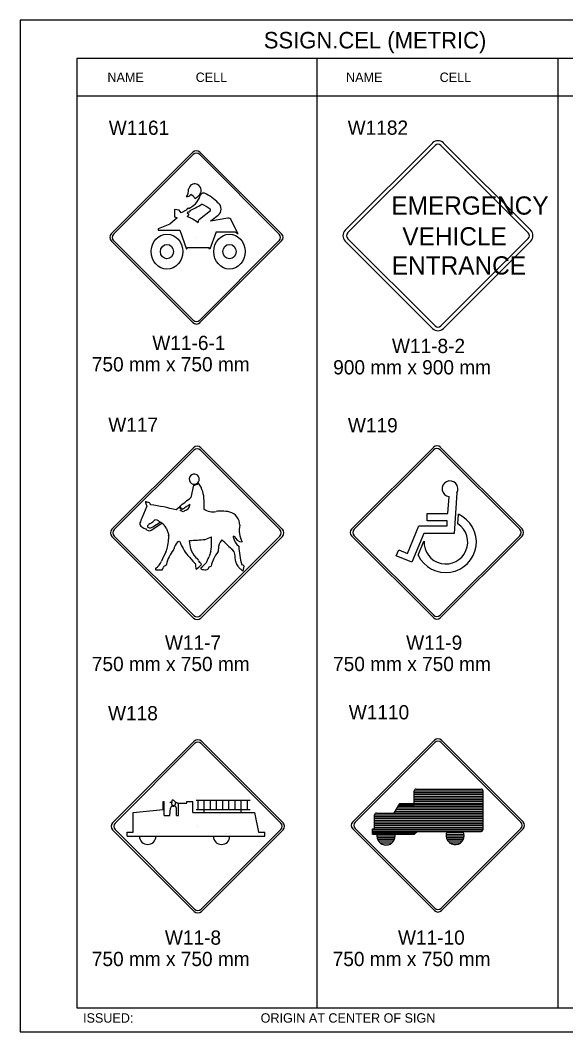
# Model space of a CAD drawing. Extents: x -12 to 6962, y -3756 to 679.
# Drawn here: x 2373.2 to 2488, y -235.4 to -22.3 of the extents above; entities that cross this region are included whole.
import ezdxf

# ---------------------------------------------------------------- set-up
doc = ezdxf.new("R2010")
doc.units = 0
for name, color, linetype in [('Level 1', 7, 'Continuous'), ('Level 2', 7, 'Continuous'), ('Level 3', 7, 'Continuous'), ('Level 62', 7, 'Continuous')]:
    doc.layers.add(name, color=color, linetype=linetype)

msp = doc.modelspace()

# ---------------------------------------------------------------- linework, layer by layer
at = {"layer": 'Level 1'}
for p, q in [((2536.79, -30.35), (2385.04, -30.35)), ((2385.04, -30.35), (2385.04, -230.35)), ((2435.62, -30.35), (2435.62, -230.35)), ((2486.28, -30.35), (2486.28, -230.35)), ((2536.79, -38.27), (2385.04, -38.27)), ((2459.93, -48.17), (2441.54, -66.55)), ((2460.46, -48.7), (2442.07, -67.08)), ((2460.46, -48.7), (2460.46, -48.7)), ((2480.08, -67.08), (2461.69, -48.7)), ((2480.61, -66.55), (2462.22, -48.17)), ((2392.31, -67.31), (2409.5, -50.12)), ((2392.81, -67.37), (2409.56, -50.62)), ((2410.93, -50.62), (2427.68, -67.37)), ((2410.99, -50.12), (2428.18, -67.31)), ((2406.21, -63.9), (2404.67, -65.27)), ((2406.6, -62.31), (2405.63, -62.15)), ((2405.63, -62.15), (2405.63, -63.69)), ((2405.63, -63.69), (2406.21, -63.9)), ((2407.03, -62.87), (2406.6, -62.31)), ((2408.22, -62.27), (2407.03, -62.87)), ((2408.49, -62.65), (2408.26, -62.87)), ((2408.26, -62.87), (2408.61, -63.17)), ((2408.61, -63.17), (2408.3, -63.69)), ((2410.87, -64.21), (2413.18, -62.37)), ((2413.32, -64.48), (2414.83, -63.37)), ((2404.67, -65.27), (2402.16, -66.22)), ((2410.58, -65), (2410.58, -64.84)), ((2416.87, -64.03), (2413.21, -64.67)), ((2413.21, -64.67), (2413.27, -64.54)), ((2419.04, -67.3), (2417.58, -64.41)), ((2402.16, -66.22), (2402.16, -66.52)), ((2402.16, -66.52), (2406.72, -66.52)), ((2406.72, -66.52), (2408.18, -70.51)), ((2410.19, -68), (2410.19, -68)), ((2414.39, -66.86), (2413.05, -70.51)), ((2414.39, -66.86), (2418.43, -66.86)), ((2418.43, -66.86), (2419.04, -67.3)), ((2460.9, -67.66), (2460.9, -67.66)), ((2409.5, -85.99), (2392.31, -68.8)), ((2409.56, -85.49), (2392.81, -68.74)), ((2408.18, -70.51), (2408.42, -70.17)), ((2408.42, -70.17), (2412.82, -70.17)), ((2427.68, -68.74), (2410.93, -85.49)), ((2428.18, -68.8), (2410.99, -85.99)), ((2413.05, -70.51), (2412.82, -70.17)), ((2441.54, -68.84), (2459.93, -87.23)), ((2442.07, -68.31), (2460.46, -86.7)), ((2461.69, -86.7), (2480.08, -68.31)), ((2462.22, -87.23), (2480.61, -68.84)), ((2392.46, -129.55), (2409.65, -112.37)), ((2392.96, -129.62), (2409.71, -112.87)), ((2411.08, -112.87), (2427.83, -129.62)), ((2411.14, -112.37), (2428.33, -129.56)), ((2442.93, -129.47), (2460.12, -112.29)), ((2443.43, -129.54), (2460.18, -112.78)), ((2461.55, -112.78), (2478.3, -129.54)), ((2461.61, -112.29), (2478.8, -129.47)), ((2409.64, -120.27), (2409.05, -122.88)), ((2463.15, -126.23), (2463.41, -122.66)), ((2465.03, -121.87), (2464.46, -130.41)), ((2399.8, -124.69), (2398.74, -127.21)), ((2406.59, -124.97), (2405.99, -125.47)), ((2407.09, -125.41), (2406.59, -124.97)), ((2406.67, -124.74), (2407.31, -125.28)), ((2406.83, -125.61), (2407.09, -125.41)), ((2407.47, -125.89), (2406.83, -125.61)), ((2402.01, -127.65), (2401.47, -127.58)), ((2458.8, -127.8), (2458.8, -126.23)), ((2458.8, -126.23), (2463.15, -126.23)), ((2463.03, -127.8), (2458.8, -127.8)), ((2462.99, -128.84), (2463.03, -127.8)), ((2465.27, -128.39), (2465.39, -126.37)), ((2400.7, -129.73), (2402.97, -128.26)), ((2401.1, -129.01), (2402.64, -128.03)), ((2403.95, -129.37), (2404.4, -130.77)), ((2454.66, -134.63), (2457.09, -128.84)), ((2457.09, -128.84), (2462.99, -128.84)), ((2409.65, -148.24), (2392.46, -131.05)), ((2409.71, -147.74), (2392.96, -130.99)), ((2406.48, -132.11), (2406.69, -132.08)), ((2409.04, -133.69), (2408.76, -131.97)), ((2410.36, -130.38), (2410.36, -130.38)), ((2427.83, -130.99), (2411.08, -147.74)), ((2428.33, -131.05), (2411.14, -148.24)), ((2415.5, -131.82), (2415.58, -131.76)), ((2417.99, -131.2), (2418.16, -130.94)), ((2460.12, -148.15), (2442.93, -130.97)), ((2460.18, -147.66), (2443.43, -130.91)), ((2458.11, -130.41), (2455.59, -136.48)), ((2456.92, -134.98), (2458.13, -132.03)), ((2464.46, -130.41), (2458.11, -130.41)), ((2460.83, -130.29), (2460.83, -130.29)), ((2460.83, -130.29), (2460.83, -130.29)), ((2478.3, -130.91), (2461.55, -147.66)), ((2478.8, -130.97), (2461.61, -148.15)), ((2413.25, -134.16), (2412.89, -135.3)), ((2418.11, -134.22), (2418.29, -134.81)), ((2452.3, -135.12), (2452.85, -133.86)), ((2452.85, -133.86), (2454.66, -134.63)), ((2455.59, -136.48), (2452.3, -135.12)), ((2401.68, -138.09), (2403.05, -138.07)), ((2409.82, -136.63), (2410.06, -136.77)), ((2410.95, -136.49), (2410.9, -136.53)), ((2412.79, -137.83), (2412.93, -137.46)), ((2412.93, -137.46), (2413.33, -137.3)), ((2419.94, -138.26), (2420.11, -138.26)), ((2420.09, -138.4), (2420.28, -137.3)), ((2392.61, -191.37), (2409.8, -174.18)), ((2393.11, -191.43), (2409.86, -174.68)), ((2411.23, -174.68), (2427.98, -191.43)), ((2411.3, -174.18), (2428.48, -191.37)), ((2443.14, -191.17), (2460.33, -173.98)), ((2443.64, -191.23), (2460.39, -174.48)), ((2461.76, -174.48), (2478.51, -191.23)), ((2461.82, -173.98), (2479.01, -191.17)), ((2456.07, -187.32), (2456.07, -184.67)), ((2456.07, -185.01), (2470.57, -185.01)), ((2456.07, -185.38), (2470.57, -185.38)), ((2456.08, -184.65), (2470.57, -184.65)), ((2456.47, -184.28), (2470.18, -184.28)), ((2470.57, -192.79), (2470.57, -184.67)), ((2403.22, -186.87), (2403.44, -186.87)), ((2403.22, -188.6), (2403.22, -186.87)), ((2403.44, -189.85), (2403.44, -186.87)), ((2404.65, -187.11), (2405.04, -187.02)), ((2405.02, -187.11), (2404.65, -187.11)), ((2406.34, -187.22), (2405.83, -187.17)), ((2406.49, -189.85), (2406.49, -187.22)), ((2406.49, -187.22), (2408.22, -187.22)), ((2408.22, -187.22), (2408.22, -186.87)), ((2408.22, -186.87), (2409.49, -186.87)), ((2409.49, -189.21), (2409.49, -186.87)), ((2410.17, -186.63), (2421.58, -186.63)), ((2410.6, -188.61), (2410.6, -186.63)), ((2411.89, -189.21), (2411.89, -186.63)), ((2413.19, -188.61), (2413.19, -186.63)), ((2414.48, -188.61), (2414.48, -186.63)), ((2415.78, -188.61), (2415.78, -186.63)), ((2417.08, -188.61), (2417.08, -186.63)), ((2418.37, -188.61), (2418.37, -186.63)), ((2419.67, -189.21), (2419.67, -186.63)), ((2420.96, -188.61), (2420.96, -186.63)), ((2451.89, -189.33), (2453.05, -187.32)), ((2453.05, -187.32), (2456.07, -187.32)), ((2456.07, -185.75), (2470.57, -185.75)), ((2456.07, -186.11), (2470.57, -186.11)), ((2456.07, -186.48), (2470.57, -186.48)), ((2456.07, -186.85), (2470.57, -186.85)), ((2456.07, -187.22), (2470.57, -187.22)), ((2456.07, -187.5), (2470.57, -187.5)), ((2396.96, -189.21), (2403.22, -188.6)), ((2396.96, -193.34), (2396.96, -189.21)), ((2404.65, -189.85), (2404.78, -188.32)), ((2405.17, -187.87), (2405.17, -187.65)), ((2405.3, -187.85), (2405.51, -187.85)), ((2405.6, -187.85), (2405.6, -187.69)), ((2406.03, -189.85), (2406.03, -188.37)), ((2409.49, -189.21), (2422.45, -189.21)), ((2410.17, -188.61), (2421.58, -188.61)), ((2422.45, -189.21), (2423.31, -193.34)), ((2448.14, -189.33), (2470.57, -189.33)), ((2452.1, -188.97), (2470.57, -188.97)), ((2452.31, -188.6), (2470.57, -188.6)), ((2452.52, -188.23), (2470.57, -188.23)), ((2452.73, -187.86), (2470.57, -187.86)), ((2452.89, -187.59), (2456.07, -187.59)), ((2403.44, -189.85), (2404.65, -189.85)), ((2406.03, -189.85), (2406.49, -189.85)), ((2447.75, -189.7), (2470.57, -189.7)), ((2447.75, -192.64), (2447.75, -189.73)), ((2447.75, -190.07), (2470.57, -190.07)), ((2447.75, -190.43), (2470.57, -190.43)), ((2447.75, -190.8), (2470.57, -190.8)), ((2447.75, -191.17), (2470.57, -191.17)), ((2447.75, -191.53), (2470.57, -191.53)), ((2409.8, -210.05), (2392.61, -192.86)), ((2409.86, -209.55), (2393.11, -192.8)), ((2395.66, -194.21), (2395.66, -193.34)), ((2395.66, -193.34), (2396.96, -193.34)), ((2410.51, -192.19), (2410.51, -192.19)), ((2427.98, -192.8), (2411.23, -209.55)), ((2428.48, -192.86), (2411.3, -210.05)), ((2423.31, -193.34), (2424.67, -193.34)), ((2424.67, -194.21), (2424.67, -193.34)), ((2460.33, -209.85), (2443.14, -192.67)), ((2460.39, -209.35), (2443.64, -192.6)), ((2447.3, -193.74), (2447.3, -192.64)), ((2447.3, -192.64), (2470.57, -192.64)), ((2447.3, -192.89), (2470.57, -192.89)), ((2447.3, -193.19), (2470.18, -193.19)), ((2447.3, -193.48), (2456.41, -193.48)), ((2447.3, -193.74), (2456.12, -193.74)), ((2447.75, -191.9), (2470.57, -191.9)), ((2447.75, -192.27), (2470.57, -192.27)), ((2456.12, -193.74), (2456.75, -193.19)), ((2461.04, -191.99), (2461.04, -191.99)), ((2478.51, -192.6), (2461.76, -209.35)), ((2479.01, -192.67), (2461.82, -209.85)), ((2462.82, -193.74), (2466.54, -193.74)), ((2462.92, -193.37), (2466.41, -193.37)), ((2395.66, -194.21), (2424.67, -194.21)), ((2448.23, -194.1), (2452.04, -194.1)), ((2448.26, -194.47), (2452.02, -194.47)), ((2448.36, -194.84), (2451.93, -194.84)), ((2448.55, -195.2), (2451.74, -195.2)), ((2448.88, -195.57), (2451.43, -195.57)), ((2462.8, -194.1), (2466.59, -194.1)), ((2462.84, -194.47), (2466.56, -194.47)), ((2462.97, -194.84), (2466.46, -194.84)), ((2463.18, -195.21), (2466.26, -195.21)), ((2463.54, -195.57), (2465.91, -195.57)), ((2385.04, -230.35), (2536.79, -230.35))]:
    msp.add_line(p, q, dxfattribs=at)
for centre, radius, start, end in [((2461.08, -49.31), 1.62, 45, 135), ((2461.08, -49.31), 0.869, 45, 135), ((2410.24, -50.87), 1.06, 45, 135), ((2410.24, -51.31), 0.969, 45, 135), ((2393.06, -68.06), 1.06, 135, 225), ((2393.49, -68.06), 0.969, 135, 225), ((2427, -68.06), 0.969, 315, 45), ((2427.43, -68.06), 1.06, 315, 45), ((2442.69, -67.7), 1.62, 135, 225), ((2442.69, -67.7), 0.869, 135, 225), ((2479.46, -67.7), 0.869, 315, 45), ((2479.46, -67.7), 1.62, 315, 45), ((2410.25, -85.24), 1.06, 225, 315), ((2410.25, -84.81), 0.969, 225, 315), ((2461.08, -86.09), 1.62, 225, 315), ((2461.08, -86.09), 0.869, 225, 315), ((2410.39, -113.12), 1.06, 45, 135), ((2410.39, -113.55), 0.969, 45, 135), ((2460.86, -113.03), 1.06, 45, 135), ((2460.86, -113.47), 0.969, 45, 135), ((2409.77, -118.99), 1.06, 118.1713, 275.6535), ((2409.77, -118.98), 1.06, 275.5881, 118.2362), ((2409.47, -118.21), 2.06, 274.6868, 307.054), ((2405.73, -123.39), 6.11, 358.9416, 35.3826), ((2463.61, -121.01), 1.66, 328.6908, 262.8479), ((2174.05, 173.92), 378.57, 307.9141, 308.371), ((2436.23, -124.94), 24.44, 176.6331, 180.7233), ((2399.76, -123.83), 0.257, 146.7081, 199.8673), ((2411.29, -119.99), 12.41, 198.422, 202.2547), ((2398.06, -126.18), 2.9, 52.185, 59.2424), ((2397.51, -121.81), 3.11, 318.268, 322.1232), ((2400.72, -123.12), 0.964, 219.179, 236.4515), ((2399.98, -124.53), 0.644, 12.6061, 71.3679), ((2394.77, -167.49), 43.49, 75.0417, 82.2834), ((2391.03, -99.49), 30.5, 302.2587, 305.747), ((2409.29, -128.28), 3.01, 113.5872, 127.2417), ((2407.25, -124.03), 1.72, 299.2334, 333.9485), ((2407.48, -124.37), 1.38, 342.6266, 5.448), ((2413.65, -122.84), 3.04, 232.4498, 284.7052), ((2415.36, -132.11), 6.4, 87.7566, 98.4957), ((2415.39, -134.48), 8.77, 77.7893, 88.5106), ((2565.91, -192.16), 179.35, 158.7661, 159.1059), ((2397.41, -123.71), 5.61, 308.197, 316.3513), ((2398.11, -134.79), 8.13, 53.3422, 61.3995), ((2416.51, -128.66), 2.85, 359.7214, 75.0471), ((2462.73, -132.24), 6.43, 205.1577, 65.6678), ((2393.21, -130.3), 1.06, 135, 225), ((2393.64, -130.3), 0.969, 135, 225), ((2398.87, -128.42), 0.565, 157.0608, 207.7097), ((2402.23, -124.66), 5.57, 226.2162, 237.0235), ((2399.56, -128.54), 0.88, 245.3069, 270.5029), ((2400.61, -128.69), 1.27, 214.7818, 232.4263), ((2400.36, -128.95), 0.912, 235.2742, 273.1903), ((2400.12, -128.92), 0.186, 139.4346, 231.9923), ((2409, -136.18), 11.66, 137.9375, 140.7176), ((2400.63, -128.4), 0.915, 226.8913, 247.0396), ((2400.38, -129.06), 0.213, 240.0892, 278.8204), ((2399.87, -126.64), 1.8, 285.3421, 304.2932), ((2399.29, -125.25), 4.17, 285.5198, 295.7017), ((2400.23, -129.05), 0.832, 282.6362, 304.6911), ((2401.16, -130.85), 3.16, 27.9681, 55.0429), ((2424.32, -129.71), 5.07, 168.2269, 209.1666), ((2427.14, -130.3), 0.969, 315, 45), ((2427.58, -130.3), 1.06, 315, 45), ((2443.68, -130.22), 1.06, 135, 225), ((2444.11, -130.22), 0.969, 135, 225), ((2462.74, -132.24), 4.6, 177.4326, 56.7718), ((2477.62, -130.22), 0.969, 315, 45), ((2478.05, -130.22), 1.06, 315, 45), ((2391.51, -130.71), 12.92, 348.365, 355.6394), ((2401.99, -131.22), 2.44, 348.6702, 10.5023), ((2408.88, -134.82), 3.62, 131.5689, 154.253), ((2417.41, -127.83), 11.53, 201.6209, 218.731), ((2408.81, -131.96), 0.0554, 88.2349, 192.3475), ((2406.65, -80.78), 51.17, 272.4189, 276.0723), ((2409.35, -122.93), 9.15, 287.2651, 296.1347), ((2400.57, -132.24), 12.86, 359.4798, 4.9258), ((2417.49, -133.5), 2.6, 139.8002, 183.2028), ((2407.65, -141.44), 12.5, 42.818, 50.6732), ((2421.53, -130.38), 3.63, 193.0381, 229.2398), ((2419.92, -130.33), 1.86, 199.1938, 269.2279), ((2400.38, -132.56), 3.86, 333.3165, 348.6329), ((2410.9, -138.43), 7.13, 140.2125, 168.2482), ((2404.77, -133.44), 0.778, 326.8035, 349.9019), ((2409.05, -134.33), 3.6, 162.4512, 167.8198), ((2409.7, -133.61), 0.667, 187.4532, 217.7848), ((2412.62, -132.78), 3.67, 199.7415, 234.6292), ((2405.27, -132.48), 8.15, 348.0996, 0.8185), ((2424.53, -141.31), 12.04, 144.0137, 152.9323), ((2414.24, -133.84), 0.671, 323.131, 16.2611), ((2450.36, -97.41), 48.85, 226.6512, 228.2213), ((2417.36, -134.49), 0.792, 19.9157, 55.4163), ((2433.27, -132.8), 14.11, 181.3592, 197.3396), ((2399.45, -134.68), 3.81, 305.9287, 335.1274), ((2420.53, -143.26), 18.96, 151.7559, 158.3993), ((2446.8, -102.31), 50.45, 220.4604, 222.8672), ((2410.08, -136.21), 0.609, 9.3735, 46.4205), ((2411.51, -135.95), 0.844, 191.1947, 223.403), ((2411.16, -135.64), 1.49, 316.7305, 344.3213), ((2403.49, -131.89), 10, 335.4653, 340.0344), ((2434.3, -143.22), 21.79, 160.1786, 164.218), ((2400.96, -138.13), 17.65, 5.6918, 10.843), ((2401.8, -137.93), 0.201, 126.6191, 233.3809), ((2401.95, -137.33), 1.33, 326.0159, 346.0634), ((2404.17, -138.11), 1.04, 110.2797, 153.3188), ((2403.77, -137), 0.144, 284.0334, 8.592), ((2402.45, -138.01), 7.71, 0.2567, 9.2691), ((2406.12, -132.3), 6.97, 305.4388, 318.2782), ((2401.13, -144.8), 12.87, 37.6583, 40.271), ((2411.42, -137.76), 0.239, 128.8546, 277.5359), ((2402.64, -127.4), 13.34, 310.3015, 316.0323), ((2412.13, -134.73), 3.33, 258.2225, 276.767), ((2412.3, -137.49), 0.599, 291.9932, 325.3317), ((2419.16, -136.36), 0.639, 182.1317, 212.8935), ((2420.47, -136.04), 1.97, 199.9477, 225.9404), ((2420.26, -136.87), 1.29, 206.8299, 235.5431), ((2416.74, -141.9), 4.84, 46.278, 54.9151), ((2419.04, -138.78), 1.93, 50.1384, 67.0034), ((2410.39, -147.49), 1.06, 225, 315), ((2410.39, -147.05), 0.969, 225, 315), ((2460.86, -147.41), 1.06, 225, 315), ((2460.86, -146.97), 0.969, 225, 315), ((2410.55, -174.93), 1.06, 45, 135), ((2410.55, -175.37), 0.969, 45, 135), ((2461.08, -174.73), 1.06, 45, 135), ((2461.08, -175.17), 0.969, 45, 135), ((2456.47, -184.67), 0.393, 90, 180), ((2470.18, -184.67), 0.393, 360, 90), ((2405.42, -187.3), 0.431, 153.1904, 18.166), ((2406.33, -187.02), 1.29, 160.1936, 180.0562), ((2405.06, -187.49), 0.908, 36.6077, 86.3698), ((2406.62, -186), 1.26, 228.7916, 256.9532), ((2405.3, -188.37), 0.518, 90, 175.1009), ((2405.51, -188.37), 0.518, 360, 90), ((2448.14, -189.73), 0.393, 90, 180), ((2393.36, -192.12), 1.06, 135, 225), ((2393.8, -192.12), 0.969, 135, 225), ((2427.3, -192.12), 0.969, 315, 45), ((2427.74, -192.12), 1.06, 315, 45), ((2443.89, -191.92), 1.06, 135, 225), ((2444.32, -191.92), 0.969, 135, 225), ((2477.83, -191.92), 0.969, 315, 45), ((2478.26, -191.92), 1.06, 315, 45), ((2450.13, -194.14), 1.9, 167.6481, 272.5939), ((2450.2, -194.2), 1.84, 270.4432, 14.6302), ((2464.73, -194.05), 1.93, 153.5236, 275.8695), ((2464.77, -194.15), 1.82, 274.923, 32.0452), ((2470.18, -192.79), 0.393, 270, 0), ((2399.98, -194.21), 1.73, 180, 0), ((2415.53, -194.21), 1.73, 180, 0), ((2410.55, -209.3), 1.06, 225, 315), ((2410.55, -208.87), 0.969, 225, 315), ((2461.08, -209.11), 1.06, 225, 315), ((2461.08, -208.67), 0.969, 225, 315)]:
    msp.add_arc(centre, radius, start, end, dxfattribs=at)
for centre, major_axis, start_param, end_param in [((2409.89, -58.28), (0, 1.51), 4.453833, 7.584155), ((2406.25, -57.98), (0, 2.6), 4.083625, 4.750842), ((2408.09, -58.06), (0, 1.44), 3.181673, 3.961079), ((2408.69, -60.45), (0, 1.45), 5.126392, 6.015145), ((2409.05, -57.25), (0, 2.77), 3.482264, 4.179125), ((2407.27, -70.03), (0, 12.47), 5.54443, 5.850815), ((2409.05, -68.46), (0, 7.82), 5.659115, 5.949632), ((2414.06, -62.09), (0, 1.54), 3.726155, 5.697602), ((2408.47, -62.19), (0, -0.286), 2.432431, 4.981886), ((2406, -71.72), (0, 8.43), 5.63585, 5.975764), ((2408.64, -62.38), (0, -0.319), 5.755144, 7.89922), ((2413.1, -62.25), (0, 0.154), 3.763298, 5.804299), ((2411.27, -64.84), (0, -0.768), 3.76321, 4.712389), ((2413.39, -64.61), (0, -0.154), 3.726146, 4.248741), ((2416.98, -64.79), (0, -0.768), 2.081251, 3.299163)]:
    msp.add_ellipse(centre, major_axis=major_axis, ratio=0.9, start_param=start_param, end_param=end_param, dxfattribs=at)
for centre, major_axis in [((2404.04, -71.05), (0, -3.68)), ((2417.2, -71.05), (0, 3.68)), ((2404.04, -71.05), (0, 1.53)), ((2417.2, -71.05), (0, -1.53))]:
    msp.add_ellipse(centre, major_axis=major_axis, ratio=0.9, dxfattribs=at)
for points in [[(2408.64, -61.98), (2410.04, -60.96), (2410.99, -59.42), (2411.52, -58.67), (2411.97, -58.7)], [(2408.92, -62.37), (2410.07, -61.83), (2411.35, -61.07)]]:
    msp.add_spline(points, degree=3, dxfattribs=at)
at = {"layer": 'Level 62'}
msp.add_lwpolyline([(2373.16, -235.4), (2548.42, -235.4), (2548.42, -22.31), (2373.16, -22.31)], close=True, dxfattribs=at)

# ---------------------------------------------------------------- texts
at = {"layer": 'Level 1'}
for s, p in [('EMERGENCY', (2451.26, -63.26)), ('VEHICLE', (2453.58, -69.75)), ('ENTRANCE', (2451.37, -75.88))]:
    msp.add_text(s, height=3.841, dxfattribs=at).set_placement(p)
at = {"layer": 'Level 2'}
for s, p in [('W1161', (2391.79, -46.45)), ('W1182', (2442.08, -46.43)), ('W117', (2391.69, -109.01)), ('W119', (2442.13, -109.13)), ('W118', (2391.64, -169.79)), ('W1110', (2442.31, -169.59))]:
    msp.add_text(s, height=3, dxfattribs=at).set_placement(p)
at = {"layer": 'Level 3'}
for s, height, p in [('SSIGN.CEL (METRIC)', 3.4642, (2424.42, -28.24)), ('NAME', 1.98, (2391.51, -35.31)), ('CELL', 1.98, (2410.09, -35.31)), ('NAME', 1.98, (2441.74, -35.31)), ('CELL', 1.98, (2461.44, -35.31)), ('W11-6-1', 3, (2400.96, -91.78)), ('W11-8-2', 3, (2451.4, -92.42)), ('750 mm x 750 mm', 3, (2388.23, -96.28)), ('900 mm x 900 mm', 3, (2439.03, -96.92)), ('W11-7', 3, (2403.61, -154.92)), ('W11-9', 3, (2454.38, -154.92)), ('750 mm x 750 mm', 3, (2388.23, -159.42)), ('750 mm x 750 mm', 3, (2439.01, -159.42)), ('W11-8', 3, (2403.61, -217.06)), ('W11-10', 3, (2452.67, -217.06)), ('750 mm x 750 mm', 3, (2388.23, -221.56)), ('750 mm x 750 mm', 3, (2438.92, -221.56)), ('ISSUED:', 1.98, (2386.38, -233.48)), ('ORIGIN AT CENTER OF SIGN', 1.9795, (2423.76, -233.48))]:
    msp.add_text(s, height=height, dxfattribs=at).set_placement(p)

doc.saveas('drawing.dxf')
